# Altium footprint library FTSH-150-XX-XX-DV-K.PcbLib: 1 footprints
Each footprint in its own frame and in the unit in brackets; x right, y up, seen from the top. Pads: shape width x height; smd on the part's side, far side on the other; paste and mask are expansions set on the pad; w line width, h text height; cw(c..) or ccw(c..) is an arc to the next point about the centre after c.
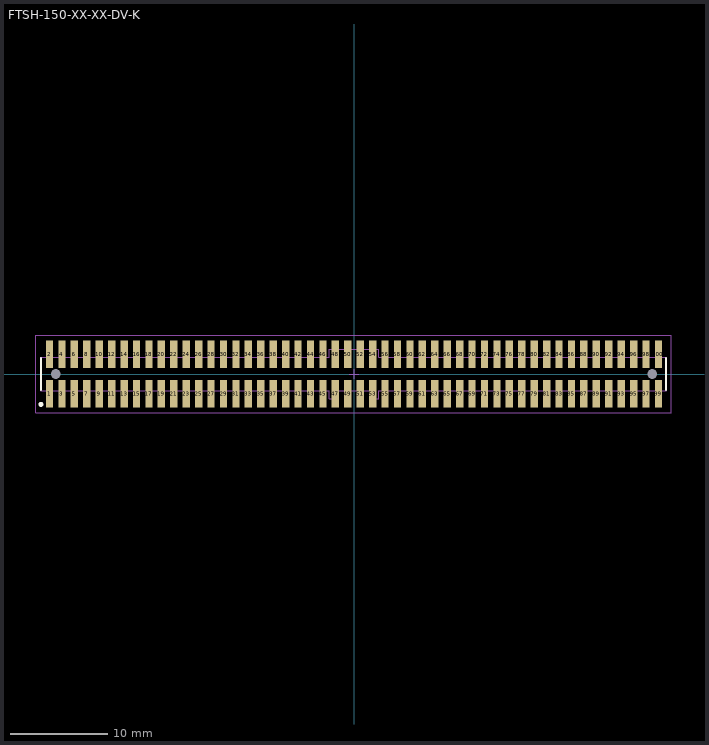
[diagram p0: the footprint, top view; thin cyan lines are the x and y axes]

## FTSH-150-XX-XX-DV-K [mm] "1.27mm pitch, 100 pin, terminal strip; vertical, w/keying shroud, SMT"
height 5.97
pads (102):
  rect 0.75x2.8 smd mask+0: 1(-31.115,-2.03) 2(-31.115,2.03) 3(-29.845,-2.03) 4(-29.845,2.03) 5(-28.575,-2.03) 6(-28.575,2.03) 7(-27.305,-2.03) 8(-27.305,2.03) 9(-26.035,-2.03) 10(-26.035,2.03) 11(-24.765,-2.03) 12(-24.765,2.03) 13(-23.495,-2.03) 14(-23.495,2.03) 15(-22.225,-2.03) 16(-22.225,2.03) 17(-20.955,-2.03) 18(-20.955,2.03) 19(-19.685,-2.03) 20(-19.685,2.03) 21(-18.415,-2.03) 22(-18.415,2.03) 23(-17.145,-2.03) 24(-17.145,2.03) 25(-15.875,-2.03) 26(-15.875,2.03) 27(-14.605,-2.03) 28(-14.605,2.03) 29(-13.335,-2.03) 30(-13.335,2.03) 31(-12.065,-2.03) 32(-12.065,2.03) 33(-10.795,-2.03) 34(-10.795,2.03) 35(-9.525,-2.03) 36(-9.525,2.03) 37(-8.255,-2.03) 38(-8.255,2.03) 39(-6.985,-2.03) 40(-6.985,2.03) 41(-5.715,-2.03) 42(-5.715,2.03) 43(-4.445,-2.03) 44(-4.445,2.03) 45(-3.175,-2.03) 46(-3.175,2.03) 47(-1.905,-2.03) 48(-1.905,2.03) 49(-0.635,-2.03) 50(-0.635,2.03) 51(0.635,-2.03) 52(0.635,2.03) 53(1.905,-2.03) 54(1.905,2.03) 55(3.175,-2.03) 56(3.175,2.03) 57(4.445,-2.03) 58(4.445,2.03) 59(5.715,-2.03) 60(5.715,2.03) 61(6.985,-2.03) 62(6.985,2.03) 63(8.255,-2.03) 64(8.255,2.03) 65(9.525,-2.03) 66(9.525,2.03) 67(10.795,-2.03) 68(10.795,2.03) 69(12.065,-2.03) 70(12.065,2.03) 71(13.335,-2.03) 72(13.335,2.03) 73(14.605,-2.03) 74(14.605,2.03) 75(15.875,-2.03) 76(15.875,2.03) 77(17.145,-2.03) 78(17.145,2.03) 79(18.415,-2.03) 80(18.415,2.03) 81(19.685,-2.03) 82(19.685,2.03) 83(20.955,-2.03) 84(20.955,2.03) 85(22.225,-2.03) 86(22.225,2.03) 87(23.495,-2.03) 88(23.495,2.03) 89(24.765,-2.03) 90(24.765,2.03) 91(26.035,-2.03) 92(26.035,2.03) 93(27.305,-2.03) 94(27.305,2.03) 95(28.575,-2.03) 96(28.575,2.03) 97(29.845,-2.03) 98(29.845,2.03) 99(31.115,-2.03) 100(31.115,2.03)
  round 0.5 hole 1 unplated mask+0: 101(-30.48,0) 102(30.48,0)
Top Overlay:
  circle w0.25: c-32,-3.1 r0.125
  lines w0.2: -32,-1.65 -32,1.65 ; 31.9,-1.65 31.9,1.65
Mechanical 12:
  lines w0.001: -32,-1.694 -32,1.7 -2.54,1.7 -2.54,2.54 2.54,2.54 2.54,1.715 31.9,1.715 31.9,-1.715 2.54,-1.715 2.54,-2.54 1.715,-2.54 1.715,-1.715 -1.715,-1.715 -1.715,-2.54 -2.54,-2.54 -2.54,-1.7 -31.994,-1.7 -32,-1.694
Mechanical 13:
  lines w0.1: -19.305,-1.715 -12.445,-1.715 ; -19.305,1.715 -12.445,1.715 ; -32,-1.694 -32,1.7 -2.54,1.7 -2.54,2.54 2.54,2.54 2.54,1.715 31.9,1.715 31.9,-1.715 2.54,-1.715 2.54,-2.54 1.715,-2.54 1.715,-1.715 -1.715,-1.715 -1.715,-2.54 -2.54,-2.54 -2.54,-1.7 -31.994,-1.7 -32,-1.694
  text ".Designator" at 0.381,0.254 h1.52
Mechanical 15:
  lines w0.05: -0.5,0 0.5,0 ; 0,-0.5 0,0.5 ; -32.5,-3.95 -32.5,3.95 32.4,3.95 32.4,-3.95 -32.5,-3.95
